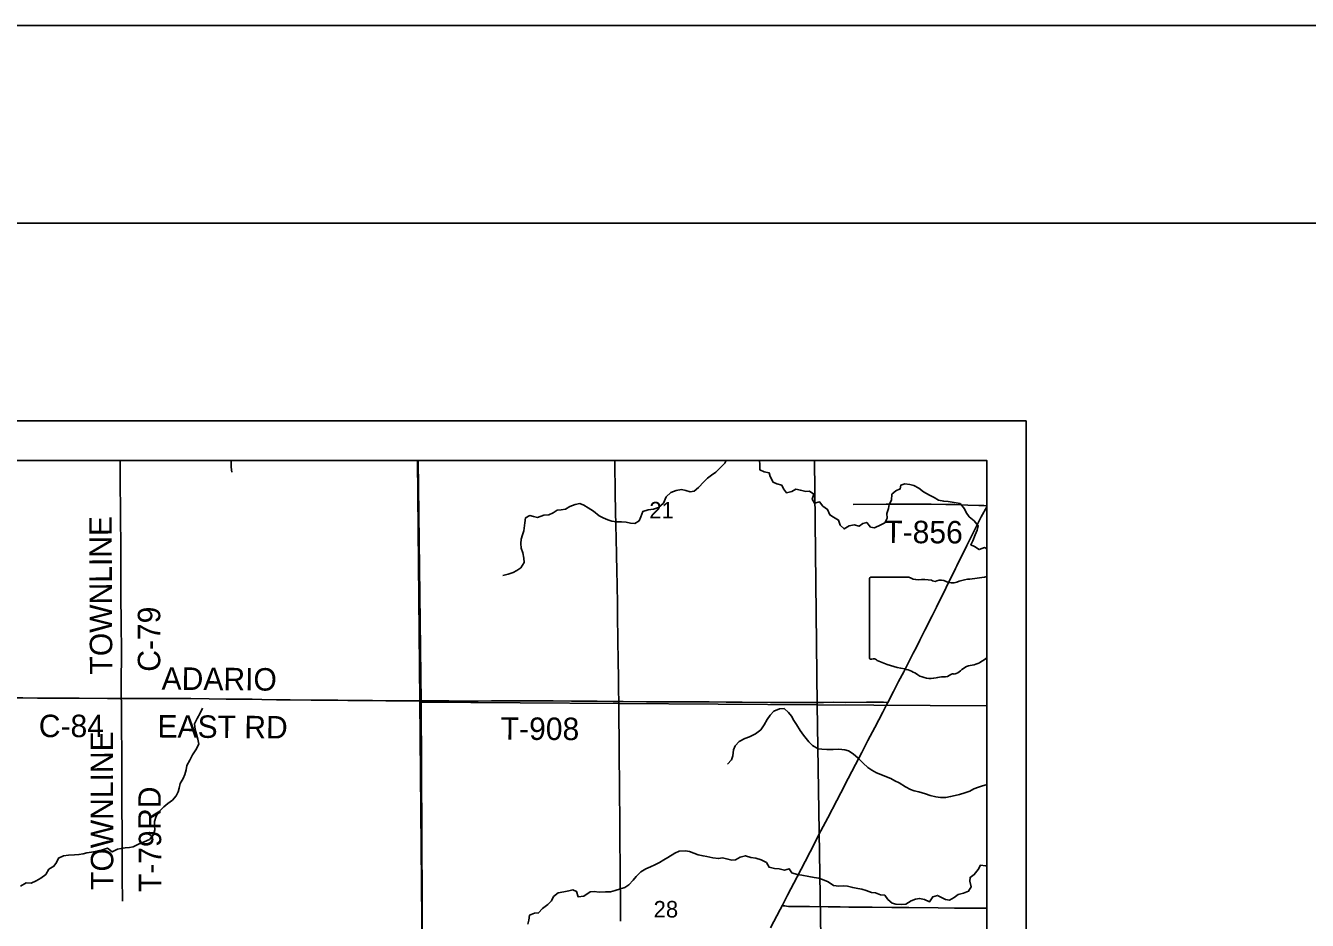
# Model space of a CAD drawing. Extents: x 0 to 34, y 0 to 22.
# Drawn here: x 6.47 to 9.711, y 19.737 to 22 of the extents above; entities that cross this region are included whole.
import ezdxf

# ---------------------------------------------------------------- set-up
doc = ezdxf.new("R2010")
doc.units = 0
for name, color, linetype in [('Default', 7, 'Continuous'), ('GM_X_County_Road', 7, 'Continuous'), ('GM_X_County_Road_Text', 7, 'Continuous'), ('GM_X_Minor_River', 7, 'Continuous'), ('GM_X_Section', 7, 'Continuous'), ('GM_X_Section_Text', 7, 'Continuous'), ('GM_X_State_Location', 7, 'Continuous'), ('GM_X_State_Route', 7, 'Continuous'), ('GM_X_Township_Road', 7, 'Continuous'), ('GM_X_Township_Road_Text', 7, 'Continuous'), ('SH_Border', 7, 'Continuous'), ('SH_Cut_Line', 7, 'Continuous'), ('SH_Data', 7, 'Continuous')]:
    doc.layers.add(name, color=color, linetype=linetype)

msp = doc.modelspace()

# ---------------------------------------------------------------- linework, layer by layer
at = {"layer": 'Default'}
for p, q in [((8.6033, 20.6013), (8.6033, 20.4012)), ((8.7031, 20.6048), (8.6065, 20.6048)), ((8.9, 20.4011), (8.9, 20.6063))]:
    msp.add_line(p, q, dxfattribs=at)
for points in [[(6.2148, 18.2783), (6.4787, 18.2762), (7.4731, 18.2617), (7.4732, 18.3097), (6.7366, 18.3097), (6.7366, 18.9662), (7.4751, 18.9662), (7.476, 19.2764), (7.4665, 20.2923), (7.4609, 20.9), (3.3847, 20.9)], [(8.9, 18.2728), (8.9, 20.9), (7.4609, 20.9), (7.4665, 20.2923), (7.476, 19.2764)]]:
    msp.add_lwpolyline(points, dxfattribs=at)
for points in [[(8.4646, 20.9), (7.4625, 20.9), (7.4702, 20.2887), (8.4715, 20.2822)], [(8.9, 20.2798), (8.9, 20.9), (8.4646, 20.9), (8.4715, 20.2822)], [(8.9, 19.2576), (8.9, 20.2798), (8.4715, 20.2822), (8.487, 19.2631)]]:
    msp.add_lwpolyline(points, close=True, dxfattribs=at)
for centre, major_axis, start_param, end_param in [((8.6071, 20.6018), (0.00382, 0), 1.727492, 3.291633), ((8.7261, 20.628), (0.037, 0), 4.042888, 4.731792), ((8.7383, 20.4924), (0.133, 0), 1.404758, 1.657859), ((8.7685, 20.6028), (0.0107, 0), 3.836095, 5.185415), ((8.7842, 20.5797), (0.0222, 0), 0.950623, 2.079405), ((8.8129, 20.6114), (0.0267, 0), 4.08156, 5.145723), ((8.8601, 20.5437), (0.0703, 0), 1.699012, 2.107814), ((8.8155, 20.8776), (0.3495, 0), 4.814394, 4.956572), ((8.6071, 20.4008), (0.00385, 0), 2.993084, 4.5083), ((8.6077, 20.4213), (0.0294, 0), 4.665946, 4.897461), ((8.6137, 20.3897), (0.0106, 0), 0.519207, 1.627899), ((8.7476, 20.5695), (0.2524, 0), 4.195997, 4.488961), ((8.8351, 20.4479), (0.0874, 0), 5.101753, 5.549358), ((8.6723, 20.3113), (0.079, 0), 0.823519, 1.323587), ((8.7577, 20.3887), (0.0501, 0), 4.026481, 4.996735), ((8.7903, 20.3737), (0.0267, 0), 4.691044, 5.507374), ((8.8145, 20.3543), (0.00752, 0), 1.147584, 2.315152), ((8.8113, 20.3818), (0.0282, 0), 4.937069, 5.64225), ((8.8719, 20.345), (0.0479, 0), 1.647645, 2.488434), ((8.7867, 20.3195), (0.0412, 0), 1.495662, 1.94098)]:
    msp.add_ellipse(centre, major_axis=major_axis, ratio=0.8, start_param=start_param, end_param=end_param, dxfattribs=at)
at = {"layer": 'GM_X_County_Road'}
for points in [[(6.7117, 20.2982), (6.7114, 20.3052), (6.7114, 20.3272), (6.7118, 20.4227), (6.7114, 20.4816), (6.7108, 20.5656), (6.7105, 20.6339), (6.7101, 20.693), (6.7099, 20.7458), (6.7089, 20.8701), (6.7085, 20.9)], [(6.3649, 20.2998), (6.4094, 20.2993), (6.4623, 20.2995), (6.4996, 20.2991), (6.6053, 20.2987), (6.6768, 20.2982), (6.7117, 20.2982)], [(6.7117, 20.2982), (6.7506, 20.2981), (6.7723, 20.2981), (6.8033, 20.2983), (6.8127, 20.2983), (6.8499, 20.2979), (6.8871, 20.2977), (6.9337, 20.297), (6.9772, 20.2964), (7.0424, 20.2959), (7.0672, 20.2957), (7.1044, 20.295), (7.1386, 20.2944), (7.1914, 20.294), (7.2224, 20.2939), (7.2596, 20.2934), (7.2845, 20.2931), (7.3186, 20.2927), (7.3466, 20.2926), (7.3807, 20.2924), (7.4667, 20.2917)]]:
    msp.add_lwpolyline(points, dxfattribs=at)
at = {"layer": 'GM_X_Minor_River'}
for points in [[(6.99, 20.9), (6.9896, 20.8958), (6.9892, 20.8829), (6.991, 20.8703)], [(8.2414, 20.9), (8.2379, 20.8934), (8.2246, 20.8801), (8.2147, 20.8706), (8.2041, 20.8627), (8.1942, 20.8551), (8.1844, 20.8464), (8.1711, 20.832), (8.1605, 20.8225), (8.1498, 20.821), (8.1388, 20.824), (8.1282, 20.8263), (8.1146, 20.824), (8.1013, 20.8191), (8.0892, 20.8081), (8.0823, 20.7918), (8.0702, 20.7808), (8.0573, 20.7766), (8.0436, 20.7751), (8.03, 20.771), (8.025, 20.7573), (8.0212, 20.7475), (8.0099, 20.7406), (7.9989, 20.7418), (7.9879, 20.7437), (7.9765, 20.7448), (7.9636, 20.7448), (7.9522, 20.7464), (7.9416, 20.7498), (7.9302, 20.7551), (7.9196, 20.7604), (7.906, 20.7722), (7.8919, 20.7805), (7.8813, 20.787), (7.8711, 20.7908), (7.8597, 20.7889), (7.8457, 20.784), (7.835, 20.7768), (7.824, 20.7756), (7.8142, 20.7745), (7.8036, 20.7677), (7.7926, 20.7624), (7.7797, 20.7613), (7.7641, 20.756), (7.7542, 20.7586), (7.7448, 20.7605), (7.7341, 20.7548), (7.7322, 20.7419), (7.7292, 20.7218), (7.7258, 20.7116), (7.7231, 20.7014), (7.722, 20.69), (7.7227, 20.6782), (7.7269, 20.6661), (7.7299, 20.6532), (7.7307, 20.6422), (7.7223, 20.6289), (7.7121, 20.6217), (7.7022, 20.6164), (7.6897, 20.6122), (7.6768, 20.6092)], [(8.3257, 20.9), (8.3262, 20.8899), (8.3259, 20.8766), (8.3372, 20.8717), (8.3497, 20.869), (8.3524, 20.8592), (8.3596, 20.8455), (8.3694, 20.8413), (8.3816, 20.8379), (8.3861, 20.828), (8.3933, 20.8182), (8.4074, 20.8216), (8.4172, 20.8273), (8.429, 20.8246), (8.4423, 20.8216), (8.4517, 20.8223), (8.4624, 20.8151), (8.4582, 20.8018), (8.4646, 20.792), (8.4775, 20.7954), (8.4859, 20.7847), (8.4976, 20.7764), (8.5033, 20.7623), (8.5128, 20.757)], [(8.5128, 20.757), (8.5253, 20.7491), (8.5294, 20.7365), (8.5393, 20.727), (8.5518, 20.735), (8.5647, 20.7369), (8.5772, 20.7338), (8.5867, 20.7407), (8.5966, 20.7433), (8.6064, 20.7312), (8.6163, 20.7297), (8.6318, 20.7376), (8.6421, 20.7422), (8.6485, 20.7543), (8.6474, 20.7657), (8.6512, 20.7789), (8.6531, 20.7884), (8.6588, 20.7998), (8.6603, 20.8146), (8.6702, 20.8229), (8.6812, 20.8279), (8.6827, 20.8373), (8.693, 20.8411), (8.7055, 20.8396), (8.7153, 20.8369), (8.7282, 20.8297), (8.74, 20.8206), (8.7555, 20.8123), (8.7669, 20.8066), (8.7783, 20.7997), (8.7912, 20.7971), (8.8022, 20.7959), (8.8124, 20.7948), (8.8223, 20.7929), (8.8325, 20.7914), (8.8435, 20.7781), (8.8477, 20.7682), (8.8556, 20.7576), (8.8685, 20.7473), (8.878, 20.7344), (8.8761, 20.7238), (8.8711, 20.7117), (8.8647, 20.6965), (8.8594, 20.687), (8.8692, 20.6825), (8.8806, 20.6745), (8.8939, 20.6798), (8.9, 20.6769)], [(6.7828, 19.9415), (6.7931, 19.9528), (6.7962, 19.9657), (6.7958, 19.976), (6.7959, 19.987), (6.8001, 20.0003), (6.8066, 20.0109), (6.8196, 20.0241), (6.8291, 20.0324), (6.8409, 20.0407), (6.8501, 20.0516), (6.8555, 20.0615), (6.8578, 20.0713), (6.8605, 20.0827), (6.8681, 20.0959), (6.8724, 20.1058), (6.8755, 20.1172), (6.877, 20.1285), (6.8851, 20.1422), (6.8916, 20.1554), (6.9, 20.1679), (6.9076, 20.1823), (6.9054, 20.1948), (6.9021, 20.2074), (6.8983, 20.2199), (6.8969, 20.2336), (6.9034, 20.2476), (6.9111, 20.2605), (6.9168, 20.2737)], [(8.2447, 20.132), (8.2545, 20.143), (8.2583, 20.1529), (8.2599, 20.1684), (8.264, 20.1783), (8.2743, 20.1893), (8.2879, 20.1965), (8.3005, 20.201), (8.3156, 20.2082), (8.3289, 20.2189), (8.3369, 20.2317), (8.3449, 20.245), (8.3521, 20.2556), (8.3619, 20.2655), (8.3756, 20.2719), (8.3877, 20.2727), (8.3991, 20.2628), (8.4059, 20.2533), (8.4124, 20.2427), (8.4188, 20.2325), (8.4283, 20.2169), (8.437, 20.2055), (8.4503, 20.1881), (8.4597, 20.1793), (8.4734, 20.171), (8.4832, 20.1694), (8.4958, 20.1691), (8.5113, 20.1691), (8.5261, 20.1694), (8.5409, 20.1679), (8.5508, 20.1656), (8.5621, 20.158), (8.5746, 20.147), (8.5875, 20.1341), (8.5997, 20.1235), (8.6095, 20.1166), (8.6216, 20.1098), (8.6361, 20.1037), (8.6463, 20.0999), (8.6573, 20.0954), (8.6675, 20.0901), (8.6785, 20.0847), (8.6948, 20.0741), (8.707, 20.0676), (8.7164, 20.0642), (8.7286, 20.0619), (8.7453, 20.057), (8.7566, 20.0528), (8.771, 20.0494), (8.7828, 20.0475), (8.7968, 20.0479), (8.8086, 20.0498), (8.8203, 20.0528), (8.831, 20.0554), (8.8446, 20.0592), (8.8575, 20.0638), (8.867, 20.0691), (8.8788, 20.074), (8.889, 20.0774), (8.8989, 20.0793), (8.9, 20.0794)], [(6.457, 19.8232), (6.4711, 19.8318), (6.484, 19.8306), (6.4966, 19.8366), (6.5083, 19.8434), (6.5209, 19.8528), (6.5286, 19.8661), (6.5411, 19.8736), (6.548, 19.8835), (6.5526, 19.8941), (6.5652, 19.9004), (6.5781, 19.9015), (6.5936, 19.9022), (6.6046, 19.9033), (6.6149, 19.9051), (6.6244, 19.9074), (6.6365, 19.9096), (6.6506, 19.9114), (6.6639, 19.9151), (6.6768, 19.9193), (6.6889, 19.9101), (6.7018, 19.9172), (6.7113, 19.9187), (6.7216, 19.9198), (6.7322, 19.9209), (6.7421, 19.9231), (6.7554, 19.9295), (6.7695, 19.9351), (6.7828, 19.9415)], [(7.7393, 19.7271), (7.7423, 19.7374), (7.7442, 19.7503), (7.7568, 19.7548), (7.7666, 19.7556), (7.7769, 19.7666), (7.7898, 19.7768), (7.7992, 19.7859), (7.8042, 19.7969), (7.8167, 19.806), (7.8307, 19.809), (7.8436, 19.8117), (7.8531, 19.8139), (7.8626, 19.8101), (7.8671, 19.7961), (7.8812, 19.7976), (7.8975, 19.8086), (7.9077, 19.8094), (7.9202, 19.8082), (7.9362, 19.8086), (7.9487, 19.8093), (7.9604, 19.8127), (7.9737, 19.8165), (7.9847, 19.8199), (7.995, 19.8264), (8.0056, 19.8381), (8.0139, 19.8476), (8.0257, 19.8598), (8.0378, 19.8673), (8.0496, 19.8723), (8.061, 19.8772), (8.0724, 19.8833), (8.0834, 19.8897), (8.0936, 19.8954), (8.1111, 19.9068), (8.1224, 19.9117), (8.1384, 19.9128), (8.1486, 19.9113), (8.1592, 19.9071), (8.1702, 19.9025), (8.1827, 19.8999), (8.1926, 19.898), (8.2078, 19.8946), (8.2218, 19.893), (8.232, 19.8949), (8.2457, 19.8919), (8.2552, 19.8892), (8.2647, 19.8896), (8.2768, 19.8968), (8.2897, 19.9002), (8.3037, 19.8956), (8.3162, 19.8941), (8.3295, 19.8899), (8.3428, 19.8835), (8.3496, 19.871), (8.3636, 19.8679), (8.375, 19.8675), (8.389, 19.8637), (8.4008, 19.8675), (8.4072, 19.8569), (8.4205, 19.8527), (8.4323, 19.8508), (8.4505, 19.8474), (8.4634, 19.8455), (8.4755, 19.8436), (8.485, 19.8405), (8.4986, 19.8341), (8.5127, 19.8246), (8.5259, 19.8234), (8.5381, 19.8238), (8.5479, 19.823), (8.5612, 19.8196), (8.5737, 19.8177), (8.5843, 19.8158), (8.5949, 19.812), (8.6086, 19.8071), (8.6185, 19.8063), (8.6317, 19.801), (8.642, 19.8006), (8.6495, 19.7896), (8.6609, 19.7801), (8.6704, 19.7778), (8.6848, 19.7767), (8.6954, 19.7778), (8.7091, 19.7865), (8.7197, 19.7907), (8.7303, 19.7922), (8.7428, 19.7895), (8.755, 19.7835), (8.7633, 19.7964), (8.7758, 19.7998), (8.7857, 19.7945), (8.7959, 19.7895), (8.8058, 19.788), (8.8176, 19.7944)], [(8.8176, 19.7944), (8.8278, 19.8024), (8.8415, 19.8058), (8.854, 19.8103), (8.8604, 19.8217), (8.8574, 19.8358), (8.8578, 19.8452), (8.8684, 19.8525), (8.8787, 19.8653), (8.884, 19.8763), (8.8969, 19.8748), (8.9, 19.8748)]]:
    msp.add_lwpolyline(points, dxfattribs=at)
at = {"layer": 'GM_X_Section'}
msp.add_lwpolyline([(8.4715, 20.2822), (8.487, 19.2631), (7.4747, 19.2711), (7.4702, 20.2887)], close=True, dxfattribs=at)
at = {"layer": 'GM_X_State_Route'}
for points in [[(8.8243, 20.6337), (8.8496, 20.6851), (8.873, 20.7324), (8.8858, 20.7573), (8.9, 20.7832)], [(8.3529, 19.7176), (8.3775, 19.7644), (8.3834, 19.7754), (8.3964, 19.8001), (8.4209, 19.8469), (8.4408, 19.8856), (8.4536, 19.9105), (8.465, 19.9325), (8.4707, 19.9435), (8.4808, 19.9628), (8.498, 19.9959), (8.5207, 20.0402), (8.5307, 20.0594), (8.5493, 20.0953), (8.568, 20.1311), (8.5838, 20.1614), (8.5995, 20.1918), (8.6168, 20.2248), (8.637, 20.2633), (8.6455, 20.28), (8.6497, 20.2881), (8.664, 20.3158), (8.677, 20.3406), (8.69, 20.3653), (8.7015, 20.3874), (8.7142, 20.4123), (8.7212, 20.4261), (8.731, 20.4456), (8.7435, 20.4706), (8.7616, 20.5067), (8.7726, 20.529), (8.8207, 20.6265), (8.8243, 20.6337)]]:
    msp.add_lwpolyline(points, dxfattribs=at)
at = {"layer": 'GM_X_Township_Road'}
for points in [[(7.9694, 20.2902), (7.9691, 20.3189), (7.9688, 20.353), (7.9683, 20.3903), (7.9667, 20.5053), (7.9663, 20.5332), (7.9653, 20.5892), (7.9646, 20.6171), (7.9634, 20.6637), (7.9626, 20.7009), (7.9618, 20.7382), (7.9613, 20.7693), (7.9606, 20.819), (7.96, 20.8936), (7.96, 20.9)], [(8.5623, 20.789), (8.6455, 20.7897), (8.6764, 20.7896), (8.7042, 20.7893), (8.7196, 20.7893), (8.7412, 20.7894), (8.7598, 20.7895), (8.7968, 20.789), (8.8185, 20.7887), (8.8524, 20.7874), (8.8802, 20.7865), (8.8925, 20.7858), (8.9, 20.7852)], [(6.7151, 19.7851), (6.7146, 19.7969), (6.7143, 19.8058), (6.7139, 19.8254), (6.7136, 19.8565), (6.7136, 19.9243), (6.7135, 19.9527), (6.7132, 20.0299), (6.7133, 20.0794), (6.7129, 20.1242), (6.713, 20.1472), (6.7129, 20.1803), (6.7125, 20.2056), (6.7123, 20.2267), (6.7123, 20.2468), (6.7121, 20.2666), (6.7121, 20.2904), (6.7117, 20.2982)], [(7.4667, 20.2917), (7.4806, 20.2919), (7.5116, 20.2918), (7.5396, 20.2917), (7.5582, 20.2914), (7.5922, 20.2914), (7.6015, 20.2914), (7.6139, 20.2915), (7.648, 20.2918), (7.6884, 20.2919), (7.7319, 20.2919), (7.7785, 20.2918), (7.8034, 20.2919), (7.85, 20.2916), (7.9152, 20.2908), (7.9556, 20.2904), (7.9694, 20.2902)], [(7.9694, 20.2902), (7.9804, 20.29), (8.0395, 20.2898), (8.0892, 20.2893), (8.1234, 20.2893), (8.17, 20.2894), (8.1979, 20.2893), (8.2414, 20.2887), (8.2818, 20.2888), (8.3533, 20.2882), (8.3968, 20.2879), (8.4278, 20.2878), (8.4558, 20.2877), (8.4744, 20.2878), (8.4869, 20.2881), (8.5117, 20.2883), (8.5428, 20.2882), (8.5956, 20.2886), (8.6266, 20.2886), (8.639, 20.2883), (8.6497, 20.2881)], [(7.9743, 19.735), (7.9736, 19.797), (7.9731, 19.8311), (7.9731, 19.8528), (7.9729, 19.8839), (7.9724, 19.9274), (7.9722, 19.9585), (7.9719, 20.0051), (7.9716, 20.0455), (7.9711, 20.0889), (7.9706, 20.1449), (7.9705, 20.1759), (7.9696, 20.266), (7.9694, 20.2878), (7.9694, 20.2902)], [(8.3834, 19.7754), (8.3864, 19.7739), (8.3894, 19.7732), (8.3934, 19.7726), (8.3985, 19.7721), (8.4087, 19.7718), (8.452, 19.7716), (8.4986, 19.7712), (8.5296, 19.7709), (8.5513, 19.7705), (8.5885, 19.7702), (8.6103, 19.7703), (8.6599, 19.7697), (8.7033, 19.7692), (8.7773, 19.7684), (8.8182, 19.7678), (8.846, 19.7679), (8.8675, 19.7677), (8.8927, 19.7674), (8.9, 19.7672)]]:
    msp.add_lwpolyline(points, dxfattribs=at)
at = {"layer": 'SH_Border'}
msp.add_lwpolyline([(1.5, 21.5), (33.5, 21.5), (33.5, 0.5), (1.5, 0.5)], close=True, dxfattribs=at)
at = {"layer": 'SH_Cut_Line'}
msp.add_lwpolyline([(0, 0), (34, 0), (34, 22), (0, 22)], close=True, dxfattribs=at)
for points in [[(7.5053, 17.3084), (7.5051, 18.039), (7.5056, 18.0926), (7.5011, 18.2616), (7.4731, 18.2617), (7.4732, 18.3097), (6.7366, 18.3097), (6.7366, 18.9662), (7.4751, 18.9662), (7.476, 19.2764), (7.4665, 20.2923), (7.4609, 20.9), (2.1, 20.9), (2.1, 14.1)], [(8.9, 14.1), (8.9, 20.9), (7.4609, 20.9), (7.4665, 20.2923), (7.476, 19.2764), (7.4751, 18.9662), (8.4483, 18.9662), (8.4483, 18.3097), (7.4732, 18.3097), (7.4731, 18.2617), (7.5011, 18.2616), (7.5056, 18.0926), (7.5051, 18.039), (7.5053, 17.3084)]]:
    msp.add_lwpolyline(points, dxfattribs=at)
at = {"layer": 'SH_Data'}
for p, q in [((2, 21), (9, 21)), ((9, 21), (9, 14)), ((2.1, 20.9), (8.9, 20.9)), ((8.9, 20.9), (8.9, 14.1))]:
    msp.add_line(p, q, dxfattribs=at)

# ---------------------------------------------------------------- texts
at = {"layer": 'GM_X_County_Road_Text'}
for s, rotation, p in [('TOWNLINE', 90.2595, (6.6891, 20.3588)), ('C-79', 90, (6.8102, 20.3656)), ('ADARIO', 359.4732, (6.8134, 20.3204)), ('C-84', 0, (6.5031, 20.2002)), ('EAST RD', 359.5093, (6.803, 20.1994))]:
    msp.add_text(s, height=0.05682, rotation=rotation, dxfattribs=at).set_placement(p)
at = {"layer": 'GM_X_Section_Text'}
for s, p in [('21', (8.0467, 20.7535)), ('28', (8.0575, 19.744))]:
    msp.add_text(s, height=0.04186, rotation=0, dxfattribs=at).set_placement(p)
at = {"layer": 'GM_X_State_Location'}
for s in ['s', 'r']:
    msp.add_text(s, height=0.000189, dxfattribs=at).set_placement((8.7644, 20.488))
msp.add_text('545', height=0.000189, rotation=0, dxfattribs=at).set_placement((8.6975, 20.4742))
at = {"layer": 'GM_X_Township_Road_Text'}
for s, rotation, p in [('T-856', 359.7234, (8.6408, 20.6911)), ('T-908', 359.7207, (7.671, 20.1936)), ('TOWNLINE', 90.1302, (6.6916, 19.8139)), ('RD', 90, (6.8116, 19.9656)), ('T-79', 90, (6.8126, 19.8081))]:
    msp.add_text(s, height=0.05682, rotation=rotation, dxfattribs=at).set_placement(p)

doc.saveas('drawing.dxf')
